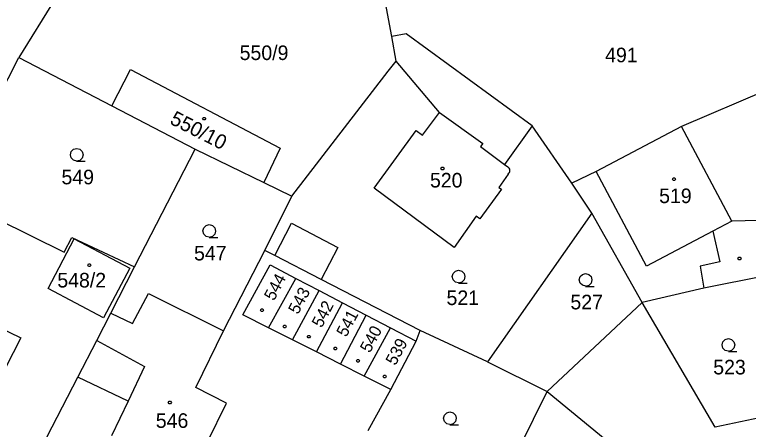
# Model space of a CAD drawing. Extents: x -621797 to -620972, y -1175539 to -1174697.
# Drawn here: x -621614.9 to -621529.4, y -1174845.9 to -1174797.6 of the extents above; entities that cross this region are included whole.
import ezdxf

# ---------------------------------------------------------------- set-up
doc = ezdxf.new("R2010")
doc.units = 0
for name, color, linetype in [('Rozvod plynu EON', 7, 'Continuous'), ('SDEL EON', 7, 'Continuous'), ('SDEL EON - popis', 7, 'Continuous'), ('Silnoproud EON', 7, 'Continuous'), ('Silnoproud EON - popis', 7, 'Continuous')]:
    doc.layers.add(name, color=color, linetype=linetype)

msp = doc.modelspace()

# ---------------------------------------------------------------- linework, layer by layer
at = {"layer": 'Rozvod plynu EON'}
for points in [[(-621592.75, -1174809.56), (-621592.66, -1174809.71), (-621592.75, -1174809.86), (-621592.93, -1174809.86), (-621593.02, -1174809.71), (-621592.93, -1174809.56)], [(-621564.95, -1174815.37), (-621564.86, -1174815.52), (-621564.95, -1174815.67), (-621565.13, -1174815.67), (-621565.22, -1174815.52), (-621565.13, -1174815.37)], [(-621537.96, -1174816.61), (-621537.87, -1174816.76), (-621537.96, -1174816.91), (-621538.14, -1174816.91), (-621538.23, -1174816.76), (-621538.14, -1174816.61)], [(-621606.14, -1174826.63), (-621606.05, -1174826.78), (-621606.14, -1174826.93), (-621606.32, -1174826.93), (-621606.41, -1174826.78), (-621606.32, -1174826.63)], [(-621530.31, -1174825.86), (-621530.22, -1174826.01), (-621530.31, -1174826.16), (-621530.49, -1174826.16), (-621530.58, -1174826.01), (-621530.49, -1174825.86)], [(-621586, -1174831.87), (-621585.91, -1174832.02), (-621586, -1174832.17), (-621586.18, -1174832.17), (-621586.27, -1174832.02), (-621586.18, -1174831.87)], [(-621583.36, -1174833.78), (-621583.27, -1174833.93), (-621583.36, -1174834.08), (-621583.54, -1174834.08), (-621583.63, -1174833.93), (-621583.54, -1174833.78)], [(-621580.54, -1174834.96), (-621580.45, -1174835.11), (-621580.54, -1174835.26), (-621580.72, -1174835.26), (-621580.81, -1174835.11), (-621580.72, -1174834.96)], [(-621577.44, -1174836.33), (-621577.35, -1174836.48), (-621577.44, -1174836.63), (-621577.62, -1174836.63), (-621577.71, -1174836.48), (-621577.62, -1174836.33)], [(-621574.8, -1174837.79), (-621574.71, -1174837.94), (-621574.8, -1174838.09), (-621574.98, -1174838.09), (-621575.07, -1174837.94), (-621574.98, -1174837.79)], [(-621571.7, -1174839.61), (-621571.61, -1174839.76), (-621571.7, -1174839.91), (-621571.88, -1174839.91), (-621571.97, -1174839.76), (-621571.88, -1174839.61)], [(-621596.76, -1174842.62), (-621596.67, -1174842.77), (-621596.76, -1174842.92), (-621596.94, -1174842.92), (-621597.03, -1174842.77), (-621596.94, -1174842.62)]]:
    msp.add_lwpolyline(points, close=True, dxfattribs=at)
at = {"layer": 'SDEL EON'}
for points in [[(-621607.7, -1174814.66), (-621608.08, -1174814.56), (-621608.35, -1174814.29), (-621608.45, -1174813.92), (-621608.35, -1174813.55), (-621608.08, -1174813.28), (-621607.71, -1174813.18), (-621607.34, -1174813.28), (-621607.07, -1174813.55), (-621606.97, -1174813.93), (-621607.07, -1174814.31), (-621607.34, -1174814.58), (-621607.72, -1174814.68), (-621606.72, -1174814.68)], [(-621592.24, -1174823.53), (-621592.62, -1174823.43), (-621592.89, -1174823.16), (-621592.99, -1174822.79), (-621592.89, -1174822.42), (-621592.62, -1174822.15), (-621592.25, -1174822.05), (-621591.88, -1174822.15), (-621591.61, -1174822.42), (-621591.51, -1174822.8), (-621591.61, -1174823.18), (-621591.88, -1174823.45), (-621592.26, -1174823.55), (-621591.26, -1174823.55)], [(-621563.16, -1174828.85), (-621563.54, -1174828.75), (-621563.81, -1174828.48), (-621563.91, -1174828.11), (-621563.81, -1174827.74), (-621563.54, -1174827.47), (-621563.17, -1174827.37), (-621562.8, -1174827.47), (-621562.53, -1174827.74), (-621562.43, -1174828.12), (-621562.53, -1174828.5), (-621562.8, -1174828.77), (-621563.18, -1174828.87), (-621562.18, -1174828.87)], [(-621548.34, -1174829.23), (-621548.72, -1174829.13), (-621548.99, -1174828.86), (-621549.09, -1174828.49), (-621548.99, -1174828.12), (-621548.72, -1174827.85), (-621548.35, -1174827.75), (-621547.98, -1174827.85), (-621547.71, -1174828.12), (-621547.61, -1174828.5), (-621547.71, -1174828.88), (-621547.98, -1174829.15), (-621548.36, -1174829.25), (-621547.36, -1174829.25)], [(-621531.68, -1174836.81), (-621532.06, -1174836.71), (-621532.33, -1174836.44), (-621532.43, -1174836.07), (-621532.33, -1174835.7), (-621532.06, -1174835.43), (-621531.69, -1174835.33), (-621531.32, -1174835.43), (-621531.05, -1174835.7), (-621530.95, -1174836.08), (-621531.05, -1174836.46), (-621531.32, -1174836.73), (-621531.7, -1174836.83), (-621530.7, -1174836.83)], [(-621564.17, -1174845.35), (-621564.55, -1174845.25), (-621564.82, -1174844.98), (-621564.92, -1174844.61), (-621564.82, -1174844.24), (-621564.55, -1174843.97), (-621564.18, -1174843.87), (-621563.81, -1174843.97), (-621563.54, -1174844.24), (-621563.44, -1174844.62), (-621563.54, -1174845), (-621563.81, -1174845.27), (-621564.19, -1174845.37), (-621563.19, -1174845.37)]]:
    msp.add_lwpolyline(points, dxfattribs=at)
at = {"layer": 'SDEL EON - popis'}
for p, q in [((-621565.39, -1174809.01), (-621560.34, -1174812.59)), ((-621531.3, -1174821.67), (-621537.17, -1174810.61)), ((-621560.34, -1174812.59), (-621560.62, -1174812.95)), ((-621560.62, -1174812.95), (-621557.82, -1174815.05)), ((-621541.26, -1174826.9), (-621547.1, -1174815.86)), ((-621584.6, -1174825.67), (-621582.66, -1174821.88)), ((-621582.66, -1174821.88), (-621577.27, -1174824.73)), ((-621531.3, -1174821.67), (-621533.53, -1174822.82)), ((-621528.17, -1174821.56), (-621531.3, -1174821.67)), ((-621533.53, -1174822.82), (-621541.26, -1174826.9)), ((-621533.53, -1174822.82), (-621532.71, -1174826.41)), ((-621577.27, -1174824.73), (-621579.21, -1174828.45)), ((-621532.71, -1174826.41), (-621534.97, -1174826.9)), ((-621534.97, -1174826.9), (-621534.58, -1174829.47)), ((-621627.85, -1174828.65), (-621614.22, -1174835.26)), ((-621614.22, -1174835.26), (-621618.74, -1174843.99)), ((-621605.38, -1174835.57), (-621599.79, -1174838.58)), ((-621599.79, -1174838.58), (-621601.72, -1174842.63)), ((-621601.72, -1174842.63), (-621607.58, -1174839.83)), ((-621601.72, -1174842.63), (-621603.65, -1174846.67))]:
    msp.add_line(p, q, dxfattribs=at)
at = {"layer": 'Silnoproud EON'}
for p, q in [((-621570.96, -1174800.15), (-621573.67, -1174785.49)), ((-621610.21, -1174795.69), (-621614.45, -1174802.6)), ((-621569.29, -1174799.84), (-621570.96, -1174800.15)), ((-621570.46, -1174803.02), (-621570.96, -1174800.15)), ((-621554.58, -1174810.53), (-621569.29, -1174799.84)), ((-621622.69, -1174818.56), (-621614.45, -1174802.6)), ((-621614.45, -1174802.6), (-621603.6, -1174808.23)), ((-621571.37, -1174804.19), (-621570.46, -1174803.02)), ((-621565.39, -1174809.01), (-621570.46, -1174803.02)), ((-621603.6, -1174808.23), (-621601.45, -1174803.97)), ((-621601.45, -1174803.97), (-621583.96, -1174813.14)), ((-621582.61, -1174818.74), (-621571.37, -1174804.19)), ((-621526.8, -1174806.18), (-621537.17, -1174810.61)), ((-621603.6, -1174808.23), (-621593.88, -1174813.28)), ((-621567.38, -1174811.62), (-621565.39, -1174809.01)), ((-621573.03, -1174817.79), (-621568.12, -1174811.1)), ((-621568.12, -1174811.1), (-621567.38, -1174811.62)), ((-621554.58, -1174810.53), (-621557.82, -1174815.05)), ((-621549.95, -1174817.23), (-621554.58, -1174810.53)), ((-621537.17, -1174810.61), (-621547.1, -1174815.86)), ((-621600.95, -1174826.99), (-621593.88, -1174813.28)), ((-621593.88, -1174813.28), (-621585.89, -1174817.15)), ((-621583.96, -1174813.14), (-621585.89, -1174817.15)), ((-621557.82, -1174815.05), (-621557.44, -1174815.33)), ((-621557.39, -1174816.16), (-621558.46, -1174817.72)), ((-621547.1, -1174815.86), (-621549.95, -1174817.23)), ((-621585.89, -1174817.15), (-621582.61, -1174818.74)), ((-621547.62, -1174820.73), (-621549.95, -1174817.23)), ((-621563.7, -1174824.71), (-621573.03, -1174817.79)), ((-621558.18, -1174817.94), (-621560.68, -1174821.39)), ((-621558.46, -1174817.72), (-621558.18, -1174817.94)), ((-621622.69, -1174818.56), (-621609.17, -1174825.28)), ((-621585.76, -1174825.08), (-621582.61, -1174818.74)), ((-621561.12, -1174821.09), (-621563.7, -1174824.71)), ((-621560.68, -1174821.39), (-621561.12, -1174821.09)), ((-621547.62, -1174820.73), (-621559.8, -1174838.05)), ((-621541.75, -1174831.14), (-621547.62, -1174820.73)), ((-621611.04, -1174829.49), (-621608, -1174823.73)), ((-621609.17, -1174825.28), (-621608.26, -1174823.56)), ((-621608.26, -1174823.56), (-621600.95, -1174826.99)), ((-621608, -1174823.73), (-621601.53, -1174827.12)), ((-621590.59, -1174834.42), (-621585.76, -1174825.08)), ((-621584.6, -1174825.67), (-621585.76, -1174825.08)), ((-621579.21, -1174828.45), (-621584.6, -1174825.67)), ((-621601.53, -1174827.12), (-621604.57, -1174832.92)), ((-621603.74, -1174832.39), (-621600.95, -1174826.99)), ((-621588.35, -1174832.55), (-621585.16, -1174826.75)), ((-621585.16, -1174826.75), (-621582.15, -1174828.32)), ((-621585.32, -1174834.08), (-621582.15, -1174828.32)), ((-621582.15, -1174828.32), (-621579.43, -1174829.73)), ((-621526.95, -1174827.96), (-621534.58, -1174829.47)), ((-621567.66, -1174834.39), (-621579.21, -1174828.45)), ((-621604.57, -1174832.92), (-621611.04, -1174829.49)), ((-621601.2, -1174833.57), (-621599.33, -1174830.1)), ((-621599.33, -1174830.1), (-621590.59, -1174834.42)), ((-621582.53, -1174835.49), (-621579.43, -1174829.73)), ((-621579.43, -1174829.73), (-621576.69, -1174831.16)), ((-621534.58, -1174829.47), (-621541.75, -1174831.14)), ((-621579.75, -1174836.89), (-621576.69, -1174831.16)), ((-621576.69, -1174831.16), (-621573.93, -1174832.59)), ((-621552.83, -1174841.5), (-621541.75, -1174831.14)), ((-621533.25, -1174845.65), (-621541.75, -1174831.14)), ((-621605.38, -1174835.57), (-621603.74, -1174832.39)), ((-621603.74, -1174832.39), (-621601.2, -1174833.57)), ((-621585.32, -1174834.08), (-621588.35, -1174832.55)), ((-621576.95, -1174838.31), (-621573.93, -1174832.59)), ((-621573.93, -1174832.59), (-621571.09, -1174834.08)), ((-621582.53, -1174835.49), (-621585.32, -1174834.08)), ((-621574.18, -1174839.7), (-621571.09, -1174834.08)), ((-621571.09, -1174834.08), (-621568.1, -1174835.63)), ((-621593.81, -1174841.03), (-621590.59, -1174834.42)), ((-621568.1, -1174835.63), (-621567.66, -1174834.39)), ((-621559.8, -1174838.05), (-621567.66, -1174834.39)), ((-621607.58, -1174839.83), (-621605.38, -1174835.57)), ((-621579.75, -1174836.89), (-621582.53, -1174835.49)), ((-621571.06, -1174841.28), (-621568.1, -1174835.63)), ((-621576.95, -1174838.31), (-621579.75, -1174836.89)), ((-621574.18, -1174839.7), (-621576.95, -1174838.31)), ((-621559.8, -1174838.05), (-621552.83, -1174841.5)), ((-621612.85, -1174850.03), (-621607.58, -1174839.83)), ((-621571.06, -1174841.28), (-621574.18, -1174839.7)), ((-621590.22, -1174842.85), (-621593.81, -1174841.03)), ((-621573.72, -1174846.05), (-621571.06, -1174841.28)), ((-621558.66, -1174853.23), (-621552.83, -1174841.5)), ((-621552.83, -1174841.5), (-621539.76, -1174852.18)), ((-621592.44, -1174847.36), (-621590.22, -1174842.85)), ((-621522.83, -1174843.48), (-621533.25, -1174845.65))]:
    msp.add_line(p, q, dxfattribs=at)
msp.add_arc((-621557.673, -1174815.761), 0.49, 305.32809, 61.56668, dxfattribs=at)

# ---------------------------------------------------------------- texts
at = {"layer": 'Silnoproud EON - popis'}
for s, p in [('550/9', (-621588.703, -1174802.88)), ('491', (-621546.073, -1174803.14)), ('549', (-621609.483, -1174817.36)), ('520', (-621566.503, -1174817.73)), ('519', (-621539.773, -1174819.55)), ('547', (-621594.023, -1174826.23)), ('548/2', (-621609.97, -1174829.38)), ('521', (-621564.573, -1174831.43)), ('527', (-621550.123, -1174831.93)), ('523', (-621533.463, -1174839.51)), ('546', (-621598.483, -1174845.74))]:
    msp.add_text(s, height=1.7, dxfattribs=at).set_placement(p)
for s, height, rotation, p in [('550/10', 1.7, 333.00307, (-621596.958, -1174810.248)), ('544', 1.4, 62.10862, (-621584.699, -1174831.017)), ('543', 1.4, 62.10862, (-621581.889, -1174832.597)), ('542', 1.4, 62.10862, (-621579.139, -1174834.167)), ('541', 1.4, 62.10862, (-621576.269, -1174835.247)), ('540', 1.4, 62.10862, (-621573.509, -1174837.087)), ('539', 1.4, 62.10862, (-621570.529, -1174838.557))]:
    msp.add_text(s, height=height, rotation=rotation, dxfattribs=at).set_placement(p)

doc.saveas('drawing.dxf')
